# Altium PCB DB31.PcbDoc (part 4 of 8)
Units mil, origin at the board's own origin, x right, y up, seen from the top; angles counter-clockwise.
Board outline 3236.22 x 4456.69 mil, 8 copper layers (Top Layer, MidLayer1, MidLayer2, GND-Layer5, MidLayer3, VCC, MidLayer4, Bottom Layer), stack 61.8 mil thick; 226 components, 469 nets, 1815 pads, 1562 vias.
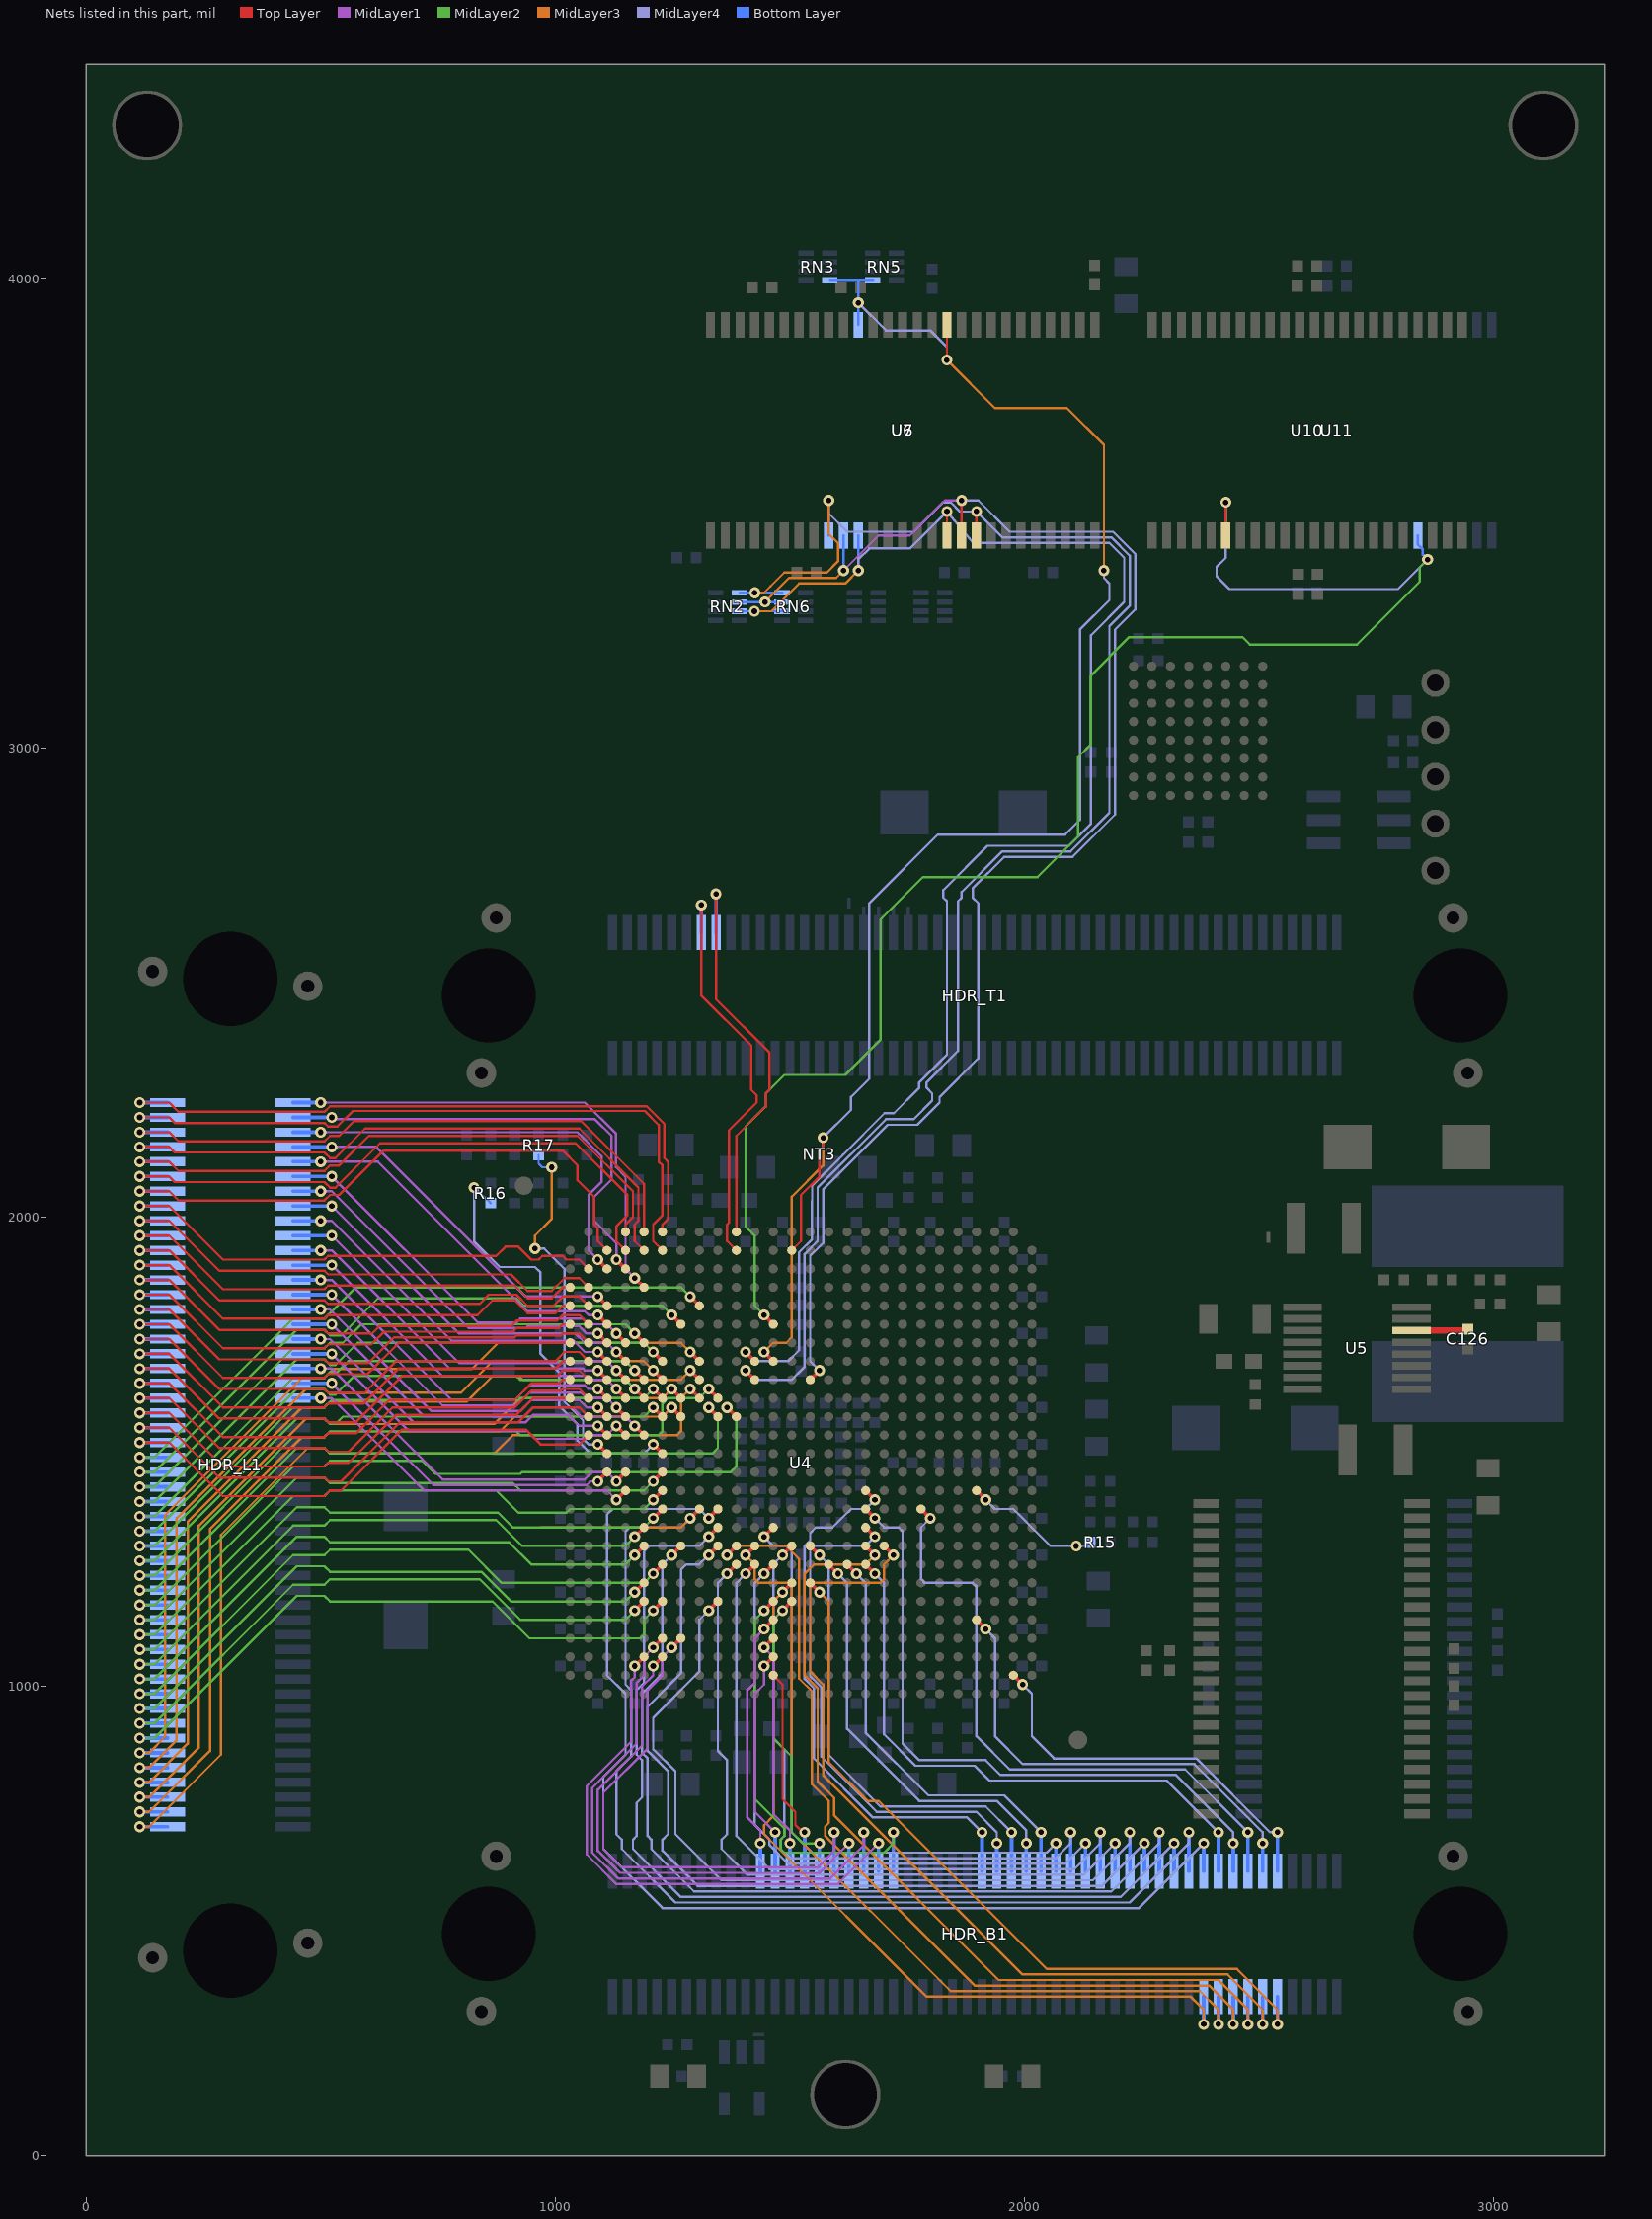
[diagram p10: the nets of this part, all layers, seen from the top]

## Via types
v1: diameter 23.62, hole 11.81, Top Layer to Bottom Layer, 947 vias
v2: diameter 23.62, hole 11.81, Top Layer to Bottom Layer, tented both sides, 476 vias
v3: diameter 27.56, hole 15.75, Top Layer to Bottom Layer, 138 vias
v4: diameter 23.62, hole 11.81, Top Layer to Bottom Layer, tented top, 1 vias

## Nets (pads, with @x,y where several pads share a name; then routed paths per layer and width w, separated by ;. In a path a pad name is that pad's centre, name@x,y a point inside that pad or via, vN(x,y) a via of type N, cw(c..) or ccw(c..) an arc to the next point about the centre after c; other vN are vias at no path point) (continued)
BUS_SDRAM_CLK: NT3.2 RN3.8 RN5.5 U4.H12 U6.38 U7.38 | length 3402.8
  Top Layer w5: NT3.2@1562.99,2141.73 1570.87,2149.61 v1(1570.87,2169.29) ; v2(1834.64,3826.77) U6.38@1834.65,3901.57
  Top Layer w7.87: v1(1444.88,1712.6) U4.H12@1464.57,1692.91
  MidLayer3 w5: v1(1444.88,1712.6) 1464.57,1732.28 1492.13,1732.28 1503.94,1744.09 1503.94,2031.49 1503.94,2039.37 1503.94,2043.31 1570.87,2110.24 v1(1570.87,2169.29) ; v2(1834.64,3826.77) 1937,3724.41 2090.55,3724.41 2169.29,3645.67 v1(2169.29,3377.95)
  MidLayer4 w5: v1(1570.87,2169.29) 1629.92,2228.35 1629.92,2255.91 1669.29,2295.28 1669.29,2669.29 1814.96,2814.96 2086.61,2814.96 2118.11,2846.46 2118.11,3251.97 2181.1,3314.96 2181.1,3350.39 2169.29,3362.2 v1(2169.29,3377.95) ; v2(1645.67,3948.82) 1704.72,3889.76 1799.21,3889.76 1834.64,3854.34 v2(1834.64,3826.77)
  Bottom Layer w5: RN3.8@1586.22,3996.06 RN5.5@1676.19,3996.06 RN5.5@1677.56,3996.06 ; U7.38@1645.67,3901.57 v2(1645.67,3948.82) 1645.67,3996.06
BUS_SDRAM_FEEDBACK: NT3.1 U4.B13 | length 221.3
  Top Layer w5: U4.B13@1503.94,1929.13 1523.62,1948.82 1523.62,2047.24 1562.99,2086.61 NT3.1@1562.99,2125.98
BUS_SDRAM_NCAS: RN2.7 RN6.6 U4.H11 U6.17 U7.17 | length 3407.4
  Top Layer w5: U6.17@1834.65,3452.76 1834.64,3499.99 v1(1834.65,3503.94)
  Top Layer w7.87: v1(1405.51,1712.6) U4.H11@1425.2,1692.91
  MidLayer3 w5: v1(1424.23,3291.34) 1460.63,3291.34 1519.68,3350.39 1618.11,3350.39 v2(1645.67,3377.95)
  MidLayer4 w5: v1(1405.51,1712.6) 1425.2,1692.91 1496.06,1692.91 1519.68,1716.54 1519.68,1925.2 1547.24,1952.76 1547.24,2031.5 1547.49,2039.37 1547.49,2067.18 1613.19,2132.87 1701.77,2221.46 1721.46,2221.46 1775.59,2275.59 1775.59,2287.4 1834.65,2346.46 1834.65,2673.23 1826.77,2681.1 1826.77,2696.85 1921.26,2791.34 2094.49,2791.34 2141.73,2838.58 2141.73,3240.16 2212.6,3311.02 2212.6,3405.51 2181.1,3437.01 1890.42,3437.01 v1(1834.65,3503.94) 1755.91,3425.2 1669.29,3425.2 1645.67,3401.57 v2(1645.67,3377.95)
  Bottom Layer w5: RN2.7@1393.3,3291.34 v1(1424.23,3291.34) RN6.6@1483.28,3291.34 RN6.6@1484.64,3291.34 ; v2(1645.67,3377.95) U7.17@1645.67,3452.76
BUS_SDRAM_NCS: RN2.5 RN6.8 U4.J11 U6.19 U7.19 | length 3648.5
  Top Layer w5: U6.19@1897.64,3452.76 v2(1897.63,3503.93)
  Top Layer w7.87: v1(1405.51,1673.23) U4.J11@1425.2,1653.54
  MidLayer3 w5: v1(1425.2,3330.71) 1444.88,3330.71 1458.54,3344.36 1488.19,3374.02 1578.74,3374.02 1602.36,3397.64 1602.36,3437.01 1582.68,3456.69 v2(1582.68,3527.56)
  MidLayer4 w5: v1(1405.51,1673.23) 1425.2,1653.54 1503.94,1653.54 1527.56,1677.16 ; 1519.68,1669.28 1531.5,1681.09 1531.5,1921.26 1559.06,1948.82 1559.06,2031.5 1559.06,2039.37 1559.06,2062.99 1704.72,2208.66 1763.78,2208.66 1803.15,2248.03 1803.15,2263.78 1791.34,2275.59 1791.34,2287.4 1858.27,2354.33 1858.27,2673.23 1866.14,2681.1 1866.14,2692.91 1952.76,2779.53 2098.43,2779.53 2181.1,2862.2 2181.1,3259.84 2224.41,3303.15 2224.41,3409.45 2185.04,3448.82 1952.76,3448.82 v2(1897.63,3503.93) 1862.21,3503.93 1842.52,3523.62 1826.77,3523.62 1763.78,3460.63 1622.05,3460.63 1582.68,3500 v2(1582.68,3527.56)
  Bottom Layer w5: RN2.5@1393.31,3330.71 v1(1425.2,3330.71) RN6.8@1483.28,3330.71 RN6.8@1484.26,3330.71 ; U7.19@1582.68,3452.76 v2(1582.68,3527.56)
BUS_SDRAM_NRAS: RN2.6 RN6.7 U4.J14 U6.18 U7.18 | length 3371.3
  Top Layer w5: U6.18@1866.14,3452.76 v1(1866.14,3527.55)
  Top Layer w7.87: U4.J14@1543.31,1653.54 v1(1562.99,1673.23)
  MidLayer1 w5: v2(1614.17,3377.95) 1688.98,3452.76 1755.91,3452.76 1830.7,3527.55 v1(1866.14,3527.55)
  MidLayer3 w5: v1(1446.86,3311.02) 1498.05,3362.2 1598.43,3362.2 v2(1614.17,3377.95)
  MidLayer4 w5: v1(1562.99,1673.23) 1543.31,1692.91 1543.31,1917.32 1570.87,1944.88 1570.87,2031.5 1570.87,2039.37 1570.87,2059.05 1708.66,2196.85 1771.65,2196.85 1818.9,2244.09 1818.9,2255.91 1901.57,2338.58 1901.57,2669.29 1889.76,2681.1 1889.76,2700.79 1956.69,2767.72 2102.36,2767.72 2192.91,2858.27 2192.91,3251.97 2236.22,3295.28 2236.22,3413.39 2188.98,3460.63 1968.5,3460.63 1901.58,3527.55 v1(1866.14,3527.55) v1@1858.27,3531.5
  Bottom Layer w5: RN2.6@1393.3,3311.02 v1(1446.86,3311.02) RN6.7@1483.28,3311.03 RN6.7@1484.64,3311.02 ; v2(1614.17,3377.95) U7.18@1614.17,3452.76
BUS_SRAM_NCS: U4.F12 U10.6 U11.6 | length 3565.7
  Top Layer w5: U10.6@2429.13,3452.76 2429.13,3503.94 v2(2429.13,3523.62)
  Top Layer w7.87: v1(1444.88,1791.34) U4.F12@1464.57,1771.65
  MidLayer2 w5: v1(1444.88,1791.34) 1425.2,1811.02 1425.2,1866.14 1425.2,1960.62 1405.51,1980.31 1405.51,2031.49 1405.51,2039.37 1405.51,2192.91 1448.82,2236.22 1448.82,2244.09 1448.82,2263.78 1488.19,2303.15 1618.11,2303.15 1692.91,2377.95 1692.91,2633.86 1783.46,2724.41 2027.56,2724.41 2114.17,2811.02 2114.17,2980.32 2141.73,3007.87 2141.73,3154.53 2223.42,3236.22 2464.57,3236.22 2480.32,3220.47 2708.66,3220.47 2842.52,3354.33 2842.52,3384.83 v2(2859.27,3401.57)
  MidLayer4 w5: v2(2429.13,3523.62) 2429.13,3405.51 2409.45,3385.83 2409.45,3366.14 2437.01,3338.58 2796.28,3338.58 v2(2859.27,3401.57)
  Bottom Layer w5: U11.6@2838.58,3452.76 2838.58,3433.42 2848.92,3423.08 2848.92,3411.92 v2(2859.27,3401.57)
BUZZER: HDR_B1.40 U4.AA12 | length 931.1
  Top Layer w7.87: v1(1444.88,1161.41) U4.AA12@1464.57,1181.1
  MidLayer2 w5: v1(1444.88,1161.41) 1425.2,1141.73 1425.2,921.26 1425.2,909.45 1425.2,759.84 1488.19,696.85 1488.19,681.1 1480.31,673.23 1480.31,653.54 1488.19,645.67 1700.79,645.67 1720.47,665.35 v2(1720.47,688.98)
  Bottom Layer w7.87: HDR_B1.40@1720.48,606.3 v2(1720.47,688.98)
CAN_RXD: HDR_T1.14 U4.B10 | length 878.4
  Top Layer w5: v2(1311.02,2665.35) 1311.02,2472.44 1417.32,2366.14 1417.32,2271.65 1429.13,2259.84 1429.13,2244.09 1370.08,2185.04 1370.08,2043.31 1370.08,2031.5 1370.08,1988.19 1366.14,1984.25 1366.14,1948.82 U4.B10@1385.83,1929.13
  Bottom Layer w7.87: HDR_T1.14@1311.02,2606.3 v2(1311.02,2665.35)
CAN_TXD: HDR_T1.16 U4.A10 | length 879.8
  Top Layer w5: v2(1342.52,2688.98) 1342.52,2464.57 1456.69,2350.39 1456.69,2271.66 1448.82,2263.78 1448.82,2236.22 1385.83,2173.23 1385.83,2043.31 1385.83,2031.5 U4.A10@1385.83,1968.5
  Bottom Layer w7.87: HDR_T1.16@1342.52,2606.3 v2(1342.52,2688.98)
COMP: C126.2 U5.6 | length 121.4
  Top Layer w13.78: U5.6@2824.58,1758.25 2942.3,1758.25 C126.2@2944.88,1760.82
CONF_DONE: R15.2 U4.R23 | length 302.6
  Top Layer w7.87: U4.R23@1897.64,1417.32 v1(1917.33,1397.64)
  MidLayer4 w5: v1(1917.33,1397.64) 1937.01,1377.95 1976.38,1377.95 2055.12,1299.21 v1(2110.24,1299.21)
  Bottom Layer w5: v1@2110.24,1307.08 v1(2110.24,1299.21) 2132.36,1299.21 R15.2@2140.23,1307.08
DATA0: R17.2 U4.N3 | length 760.6
  Top Layer w7.87: v1(1090.55,1515.75) U4.N3@1110.24,1496.06
  MidLayer3 w5: v1(956.69,1933.07) 956.69,1960.63 992.13,1996.06 v1(992.13,2106.3)
  MidLayer4 w5: v1(956.69,1933.07) 976.38,1933.07 1019.69,1889.76 1019.69,1606.3 1059.06,1566.93 1059.06,1527.56 1070.87,1515.75 v1(1090.55,1515.75)
  Bottom Layer w5: R17.2@964.56,2132.36 964.56,2114.18 972.44,2106.3 v1(992.13,2106.3)
DAU_RESET_SW: HDR_B1.38 U4.AD5 | length 1214.9
  Top Layer w7.87: v1(1169.29,1043.3) U4.AD5@1188.98,1062.99
  MidLayer1 w5: v1(1169.29,1043.3) 1169.29,1019.68 1161.42,1011.81 1161.42,921.26 1161.42,909.45 1161.42,881.89 1066.93,787.4 1066.93,641.73 1129.92,578.74 1602.36,578.74 v2(1688.98,665.35)
  Bottom Layer w7.87: HDR_B1.38@1688.98,606.3 v2(1688.98,665.35)
DAU_TFT_BLIGHT: HDR_B1.91 U4.Y14 | length 1664
  Top Layer w7.87: U4.Y14@1543.31,1220.47 v1(1562.99,1200.78)
  MidLayer3 w5: v1(1562.99,1200.78) 1582.68,1181.1 1582.68,921.26 1582.68,909.45 1582.68,838.58 1665.35,755.91 1688.98,755.91 2047.24,397.64 2452.76,397.64 2539.37,311.02 v2(2539.37,279.53)
  Bottom Layer w7.87: v2(2539.37,279.53) HDR_B1.91@2539.37,338.58
DAU_TFT_BLUE0: HDR_B1.62 U4.U12 | length 1346.5
  Top Layer w7.87: v1(1444.88,1318.9) U4.U12@1464.57,1338.58
  MidLayer4 w5: v1(1444.88,1318.9) 1464.57,1299.21 1492.13,1299.21 1503.94,1287.4 1503.94,921.26 1503.94,909.45 1503.94,688.98 1547.24,645.67 2047.24,645.67 v2(2066.93,665.35)
  Bottom Layer w7.87: HDR_B1.62@2066.93,606.3 v2(2066.93,665.35)
DAU_TFT_BLUE1: HDR_B1.64 U4.V13 | length 1420.6
  Top Layer w7.87: v1(1484.25,1279.53) U4.V13@1503.94,1299.21
  MidLayer4 w5: v1(1484.25,1279.53) 1464.57,1259.84 1464.57,921.26 1464.57,909.45 1464.57,889.76 1488.19,866.14 1488.19,681.1 1480.31,673.23 1480.31,653.54 1500,633.86 2066.93,633.86 2098.42,665.35 v2(2098.42,688.98)
  Bottom Layer w7.87: v2(2098.42,688.98) HDR_B1.64@2098.43,606.3
DAU_TFT_BLUE2: HDR_B1.66 U4.W12 | length 1394.3
  Top Layer w7.87: v1(1444.88,1240.16) U4.W12@1464.57,1259.84
  MidLayer4 w5: v1(1444.88,1240.16) 1425.2,1220.47 1425.2,921.26 1425.2,909.45 1425.2,704.72 1456.69,673.23 1456.69,661.42 1496.06,622.05 2086.62,622.05 v2(2129.92,665.35)
  Bottom Layer w7.87: HDR_B1.66@2129.92,606.3 v2(2129.92,665.35)
DAU_TFT_BLUE3: HDR_B1.68 U4.W11 | length 1529.1
  Top Layer w7.87: v1(1405.51,1240.16) U4.W11@1425.2,1259.84
  MidLayer4 w5: v1(1405.51,1240.16) 1385.83,1220.47 1385.83,921.26 1385.83,909.45 1385.83,681.1 1456.69,610.24 2106.3,610.24 2161.42,665.35 v2(2161.42,688.98)
  Bottom Layer w7.87: HDR_B1.68@2161.42,606.3 v2(2161.42,688.98)
DAU_TFT_BLUE4: HDR_B1.70 U4.W10 | length 1583.8
  Top Layer w7.87: v1(1366.14,1240.16) U4.W10@1385.83,1259.84
  MidLayer4 w5: v1(1366.14,1240.16) 1346.46,1220.47 1346.46,921.26 1346.46,909.45 1346.46,862.2 1366.14,842.52 1366.14,685.04 1354.33,673.23 1354.33,653.54 1409.45,598.43 2125.98,598.43 v2(2192.91,665.35)
  Bottom Layer w7.87: HDR_B1.70@2192.92,606.3 v2(2192.91,665.35)
DAU_TFT_CL1: HDR_B1.88 U4.T20 | length 1355.7
  Top Layer w7.87: U4.T20@1779.53,1377.95 v1(1799.22,1358.27)
  MidLayer4 w5: v1(1799.22,1358.27) 1779.53,1338.58 1779.53,1228.35 1787.4,1220.47 1889.76,1220.47 1897.64,1212.6 1897.64,921.26 1897.64,911.26 1897.64,893.7 1968.5,822.83 2342.52,822.83 v2@2476.38,688.98
  Bottom Layer w7.87: HDR_B1.88@2476.38,606.3 v2(2476.38,688.98)
DAU_TFT_CL2: HDR_B1.90 U4.AB23 | length 1061.7
  Top Layer w7.87: U4.AB23@1897.64,1141.73 v1(1917.33,1122.04)
  MidLayer4 w5: v1(1917.33,1122.04) 1937.01,1102.36 1937.01,921.26 1937.01,909.45 1937.01,893.7 1996.06,834.65 2362.2,834.65 2507.87,688.98 v2(2507.87,665.35)
  Bottom Layer w7.87: v2(2507.87,665.35) HDR_B1.90@2507.88,606.3 v2(2507.87,665.35)
DAU_TFT_CL3: HDR_B1.92 U4.AE25 | length 837.3
  Top Layer w7.87: U4.AE25@1976.38,1023.62 v1(1996.07,1003.94)
  MidLayer4 w5: v1(1996.07,1003.94) 2015.75,984.25 2015.75,921.26 2015.75,909.45 2015.75,893.7 2062.99,846.46 2366.14,846.46 2523.62,688.98 v2(2539.37,688.98)
  Bottom Layer w7.87: HDR_B1.92@2539.37,606.3 v2(2539.37,688.98)
DAU_TFT_DISP_ON: HDR_B1.89 U4.V18 | length 1898.8
  Top Layer w7.87: U4.V18@1700.79,1299.21 v1(1720.47,1279.53)
  MidLayer3 w5: v1(1720.47,1279.53) 1700.79,1259.84 1700.79,1228.35 1692.91,1220.47 1551.18,1220.47 1543.31,1212.6 1543.31,1031.49 1570.87,1003.94 1570.87,921.26 1570.87,909.45 1570.87,811.02 1996.06,385.83 2433.07,385.83 2507.87,311.02 v2(2507.88,279.53)
  Bottom Layer w7.87: v2(2507.88,279.53) HDR_B1.89@2507.88,338.58
DAU_TFT_GREEN0: HDR_B1.72 U4.AA9 | length 1720.9
  Top Layer w7.87: v1(1326.77,1161.42) U4.AA9@1346.46,1181.1
  MidLayer4 w5: v1(1326.77,1161.42) 1307.09,1141.73 1307.09,1031.5 1208.66,933.07 1208.66,921.26 1208.66,909.45 1208.66,866.14 1255.91,818.9 1255.91,685.04 1354.33,586.61 2145.67,586.61 2224.41,665.36 v2(2224.41,688.98)
  Bottom Layer w7.87: HDR_B1.72@2224.41,606.3 v2(2224.41,688.98)
DAU_TFT_GREEN1: HDR_B1.74 U4.V9 | length 1905.7
  Top Layer w7.87: v1(1326.77,1279.53) U4.V9@1346.46,1299.21
  MidLayer4 w5: v1(1326.77,1279.53) 1307.09,1259.84 1279.53,1259.84 1267.72,1248.03 1267.72,1027.56 1196.85,956.69 1196.85,921.26 1196.85,909.45 1196.85,862.2 1240.16,818.9 1240.16,685.04 1228.35,673.23 1228.35,649.61 1303.15,574.8 2165.35,574.8 v2(2255.9,665.35)
  Bottom Layer w7.87: HDR_B1.74@2255.91,606.3 v2(2255.9,665.35)
DAU_TFT_GREEN2: HDR_B1.76 U4.V7 | length 1957
  Top Layer w7.87: v1(1248.03,1279.53) U4.V7@1267.72,1299.21
  MidLayer4 w5: v1(1248.03,1279.53) 1228.35,1259.84 1228.35,1027.56 1185.04,984.25 1185.04,921.26 1185.04,909.45 1185.04,858.27 1196.85,846.46 1196.85,681.1 1204.72,673.23 1204.72,653.54 1295.28,562.99 2185.04,562.99 2287.4,665.35 v2(2287.4,688.98)
  Bottom Layer w7.87: HDR_B1.76@2287.41,606.3 v2(2287.4,688.98)
DAU_TFT_GREEN3: HDR_B1.78 U4.U9 | length 2134.4
  Top Layer w7.87: v1(1326.77,1318.9) U4.U9@1346.46,1338.58
  MidLayer4 w5: v1(1326.77,1318.9) 1307.09,1299.21 1200.79,1299.21 1188.98,1287.4 1188.98,1007.87 1173.23,992.13 1173.23,921.26 1173.23,909.45 1173.23,854.33 1185.04,842.52 1185.04,763.78 1173.23,751.97 1173.23,681.1 1165.35,673.23 1165.35,653.54 1267.72,551.18 2204.72,551.18 v2(2318.9,665.35)
  Bottom Layer w7.87: HDR_B1.78@2318.9,606.3 v2(2318.9,665.35)
DAU_TFT_GREEN4: HDR_B1.80 U4.T8 | length 2618.5
  Top Layer w7.87: v1(1287.4,1358.27) U4.T8@1307.09,1377.95
  MidLayer3 w5: 968.51,1338.58 1267.72,1338.58 v1(1287.4,1358.27)
  MidLayer4 w5: v1(1287.4,1358.27) 1267.72,1338.58 1157.48,1338.58 1149.61,1330.71 1149.61,1003.94 1161.42,992.13 1161.42,921.26 1161.42,909.45 1161.42,850.39 1129.92,818.9 1129.92,685.04 1141.73,673.23 1141.73,653.54 1255.91,539.37 2224.41,539.37 2350.39,665.35 v2(2350.39,688.98)
  Bottom Layer w7.87: HDR_B1.80@2350.4,606.3 v2(2350.39,688.98)
DAU_TFT_GREEN5: HDR_B1.82 U4.T9 | length 2453.7
  Top Layer w7.87: v1(1326.77,1358.27) U4.T9@1346.46,1377.95
  MidLayer4 w5: v1(1326.77,1358.27) 1307.09,1377.95 1122.05,1377.95 1110.24,1366.14 1110.24,1023.62 1149.61,984.25 1149.61,921.26 1149.61,909.45 1149.61,854.33 1102.36,807.09 1102.36,653.54 1228.35,527.56 2244.09,527.56 v2(2381.89,665.35)
  Bottom Layer w7.87: HDR_B1.82@2381.89,606.3 v2(2381.89,665.35)
DAU_TFT_IRQ: HDR_B1.81 U4.Y13 | length 1742.4
  Top Layer w7.87: v1(1484.25,1200.78) U4.Y13@1503.94,1220.47
  MidLayer3 w5: v1(1484.25,1200.78) 1464.57,1181.1 1464.57,921.26 1464.57,909.45 1464.57,723.43 1444.88,703.74 1444.88,685.04 1791.34,338.58 2354.33,338.58 2381.89,311.02 v2(2381.89,279.53)
  Bottom Layer w7.87: v2(2381.89,279.53) HDR_B1.81@2381.89,338.58
DAU_TFT_M: HDR_B1.87 U4.V17 | length 1879.3
  Top Layer w7.87: U4.V17@1661.42,1299.21 v1(1681.1,1279.53)
  MidLayer3 w5: v1(1681.1,1279.53) 1661.42,1259.84 1551.18,1259.84 1531.5,1240.16 1531.5,1160.43 1531.5,1023.62 1559.06,996.06 1559.06,921.26 1559.06,909.45 1559.06,797.24 1594.49,761.81 1594.49,724.41 1944.88,374.02 2413.39,374.02 2476.38,311.02 v2(2476.38,279.53)
  Bottom Layer w7.87: v2(2476.38,279.53) HDR_B1.87@2476.38,338.58
DAU_TFT_MUX: HDR_B1.85 U4.V10 | length 1934.8
  Top Layer w7.87: v1(1366.14,1279.53) U4.V10@1385.83,1299.21
  MidLayer3 w5: v1(1366.14,1279.53) 1385.83,1299.21 1492.13,1299.21 1519.68,1271.65 1519.68,1016.73 1547.24,989.17 1547.24,921.26 1547.24,909.45 1547.24,791.34 1582.68,755.91 1582.68,708.66 1574.8,700.79 1574.8,681.1 1893.7,362.2 2393.7,362.2 2444.88,311.02 v2(2444.88,279.53)
  Bottom Layer w7.87: v2(2444.88,279.53) HDR_B1.85@2444.89,338.58
DAU_TFT_POL: HDR_B1.83 U4.V11 | length 1852.6
  Top Layer w7.87: v1(1405.51,1279.53) U4.V11@1425.2,1299.21
  MidLayer3 w5: v1(1405.51,1279.53) 1425.2,1259.84 1425.2,1228.35 1433.07,1220.47 1496.06,1220.47 1503.94,1212.6 1503.94,921.26 1503.94,909.45 1503.94,688.98 1842.52,350.39 2374.02,350.39 2413.39,311.03 v2(2413.39,279.53)
  Bottom Layer w7.87: v2(2413.39,279.53) HDR_B1.83@2413.39,338.58
DAU_TFT_RED0: HDR_B1.52 U4.R17 | length 1194.5
  Top Layer w7.87: U4.R17@1661.42,1417.32 v1(1681.1,1397.64)
  MidLayer4 w5: v1(1681.1,1397.64) 1661.42,1377.95 1629.92,1377.95 1590.55,1338.58 1555.12,1338.58 1543.31,1326.77 1543.31,1311.02 1531.5,1299.21 1531.5,1015.75 1551.18,996.06 1551.18,921.26 1551.18,909.45 1551.18,846.46 1677.17,720.47 1870.08,720.47 1877.95,720.47 v2(1909.45,688.98)
  Bottom Layer w7.87: HDR_B1.52@1909.45,606.3 v2(1909.45,688.98)
DAU_TFT_RED1: HDR_B1.54 U4.U17 | length 1151.3
  Top Layer w7.87: U4.U17@1661.42,1338.58 v1(1681.1,1318.9)
  MidLayer4 w5: v1(1681.1,1318.9) 1661.42,1299.21 1551.18,1299.21 1543.31,1291.34 1543.31,1021.65 1566.93,998.03 1566.93,921.26 1566.93,909.45 1566.93,850.39 1685.04,732.28 1897.64,732.28 1940.94,688.98 v2(1940.94,665.35)
  Bottom Layer w7.87: HDR_B1.54@1940.95,606.3 v2(1940.94,665.35)
DAU_TFT_RED2: HDR_B1.56 U4.V14 | length 1002.1
  Top Layer w7.87: U4.V14@1543.31,1299.21 v1(1562.99,1279.53)
  MidLayer4 w5: v1(1562.99,1279.53) 1582.68,1259.84 1582.68,921.26 1582.68,909.45 1582.68,854.33 1692.91,744.1 1881.89,744.1 1917.32,744.09 v2(1972.44,688.98)
  Bottom Layer w7.87: HDR_B1.56@1972.44,606.3 v2(1972.44,688.98)
DAU_TFT_RED3: HDR_B1.58 U4.W15 | length 924.9
  Top Layer w7.87: U4.W15@1582.68,1259.84 v1(1602.36,1240.16)
  MidLayer4 w5: v1(1602.36,1240.16) 1622.05,1220.47 1622.05,921.26 1622.05,909.45 1775.59,755.91 1940.94,755.91 2003.94,692.92 v2(2003.94,665.35)
  Bottom Layer w7.87: HDR_B1.58@2003.94,606.3 v2(2003.94,665.35)
DAU_TFT_RED4: HDR_B1.60 U4.W16 | length 935.1
  Top Layer w7.87: U4.W16@1622.05,1259.84 v1(1641.73,1240.16)
  MidLayer4 w5: v1(1641.73,1240.16) 1661.42,1220.47 1661.42,921.26 1661.42,910.43 1661.42,901.57 1795.28,767.71 1956.69,767.71 ; 1940.94,767.72 1956.69,767.72 ; v2(2035.43,688.98) 1956.69,767.71
  Bottom Layer w7.87: HDR_B1.60@2035.44,606.3 v2(2035.43,688.98)
DAU_TFT_STH: HDR_B1.86 U4.T17 | length 1416.7
  Top Layer w7.87: U4.T17@1661.42,1377.95 v1(1681.1,1358.27)
  MidLayer4 w5: v1(1681.1,1358.27) 1700.79,1338.58 1732.28,1338.58 1740.16,1330.71 1740.16,921.26 1740.16,909.45 1740.16,877.95 1775.59,842.52 1917.32,842.52 1948.82,811.02 2322.84,811.02 2444.88,688.98 v2(2444.88,665.35)
  Bottom Layer w7.87: HDR_B1.86@2444.89,606.3 v2(2444.88,665.35)
DAU_TFT_STV: HDR_B1.84 U4.W17 | length 1260.2
  Top Layer w7.87: U4.W17@1661.42,1259.84 v1(1681.1,1240.16)
  MidLayer4 w5: v1(1681.1,1240.16) 1700.79,1220.47 1700.79,921.26 1700.79,911.26 1700.79,897.64 1767.72,830.71 1893.7,830.71 1925.2,799.21 2303.15,799.21 v2@2413.38,688.98
  Bottom Layer w7.87: HDR_B1.84@2413.39,606.3 v2(2413.38,688.98)
DCLK: R16.2 U4.N6 | length 931.9
  Top Layer w7.87: v1(1208.66,1515.75) U4.N6@1228.35,1496.06
  MidLayer4 w5: v1(826.77,2062.99) 826.77,1948.6 881.67,1893.7 956.69,1893.7 968.5,1881.89 968.5,1708.66 1007.87,1669.29 1007.87,1598.42 1047.24,1559.05 1047.24,1523.62 1059.88,1510.98 1074.8,1496.06 1188.98,1496.06 v1(1208.66,1515.75)
  Bottom Layer w5: v1(826.77,2062.99) 860.7,2031.5 R16.2@862.2,2030
DIP0: HDR_B1.22 U4.AB12 | length 569.7
  Top Layer w7.87: v1(1444.88,1122.04) U4.AB12@1464.57,1141.73
  MidLayer1 w5: v2(1437.01,665.35) 1437.01,692.91 1409.45,720.47 1409.45,909.45 1409.45,921.26 1409.45,992.13 1425.2,1007.87 1425.2,1102.36 v1(1444.88,1122.04)
  Bottom Layer w7.87: HDR_B1.22@1437.01,606.3 v2(1437.01,665.35)
DIP1: HDR_B1.24 U4.AD12 | length 490.9
  Top Layer w7.87: v1(1444.88,1043.3) U4.AD12@1464.57,1062.99
  MidLayer1 w5: v1(1444.88,1043.3) 1444.88,1003.93 1425.2,984.25 1425.2,921.26 1425.2,909.45 1425.2,732.28 v2(1468.5,688.98)
  Bottom Layer w7.87: HDR_B1.24@1468.51,606.3 v2(1468.5,688.98)
DIP2: HDR_B1.26 U4.AC12 | length 527
  Top Layer w7.87: v1(1444.88,1082.67) U4.AC12@1464.57,1102.36
  MidLayer1 w5: v1(1444.88,1082.67) 1464.57,1062.99 1464.57,921.26 1464.57,909.45 1464.57,728.35 1500,692.91 v2(1500,665.35)
  Bottom Layer w7.87: HDR_B1.26@1500,606.3 v2(1500,665.35)
DIP3: HDR_B1.28 U4.AE12 | length 447.4
  Top Layer w5: U4.AE12@1464.57,1023.62 1484.25,1003.93 1484.25,921.26 1484.25,909.45 1484.25,759.84 1511.81,732.28 1511.81,704.72 1527.56,688.98 v2(1531.5,688.98)
  Bottom Layer w7.87: HDR_B1.28@1531.5,606.3 v2(1531.5,688.98)
DIP4: HDR_B1.30 U4.AA13 | length 652.6
  Top Layer w7.87: v1(1484.25,1161.41) U4.AA13@1503.94,1181.1
  MidLayer2 w5: v1(1484.25,1161.41) 1464.57,1141.73 1464.57,921.26 1464.57,909.45 1464.57,889.76 1503.94,850.39 1503.94,688.98 1527.56,665.35 v2(1562.99,665.35)
  Bottom Layer w7.87: HDR_B1.30@1562.99,606.3 v2(1562.99,665.35)
DIP5: HDR_B1.32 U4.AC7 | length 1162.5
  Top Layer w7.87: v1(1248.03,1082.67) U4.AC7@1267.72,1102.36
  MidLayer1 w5: v1(1248.03,1082.67) 1228.35,1062.99 1228.35,1023.62 1196.85,992.12 1196.85,921.26 1196.85,909.45 1196.85,867.82 1102.36,773.33 1102.36,653.54 1141.73,614.17 1559.06,614.17 1594.49,649.61 v2(1594.49,688.98)
  Bottom Layer w7.87: HDR_B1.32@1594.49,606.3 v2(1594.49,688.98)
DIP6: HDR_B1.34 U4.AD6 | length 1110.6
  Top Layer w7.87: v1(1208.66,1043.3) U4.AD6@1228.35,1062.99
  MidLayer1 w5: v1(1208.66,1043.3) 1208.66,1023.62 1185.04,1000 1185.04,921.26 1185.04,909.45 1185.04,874.02 1090.55,779.53 1090.55,649.61 1137.8,602.36 1562.99,602.36 v2(1625.98,665.35)
  Bottom Layer w7.87: HDR_B1.34@1625.99,606.3 v2(1625.98,665.35)
DIP7: HDR_B1.36 U4.AC6 | length 1259.8
  Top Layer w7.87: v1(1208.66,1082.67) U4.AC6@1228.35,1102.36
  MidLayer1 w5: v1(1208.66,1082.67) 1188.98,1062.99 1188.98,1023.62 1173.23,1007.87 1173.23,921.26 1173.23,909.45 1173.23,877.95 1078.74,783.46 1078.74,645.67 1133.86,590.55 1586.61,590.55 1657.48,661.42 v2(1657.48,688.98)
  Bottom Layer w7.87: HDR_B1.36@1657.48,606.3 v2(1657.48,688.98)
EXTEND_A0: HDR_L1.1 U4.A6 | length 1467.7
  Top Layer w5: v2(114.17,2244.09) 177.17,2244.09 196.85,2224.41 409.45,2224.41 ; 385.83,2224.41 507.88,2224.41 519.69,2236.22 1194.66,2236.22 1232.28,2198.6 1232.28,2125.98 1240.16,2118.11 1240.16,2043.31 1240.16,2031.5 1240.16,1996.06 1228.35,1984.25 U4.A6@1228.35,1968.5
  Bottom Layer w7.87: v2(114.17,2244.09) HDR_L1.1@173.23,2244.09
EXTEND_A1: HDR_L1.3 U4.B6 | length 1533.7
  Top Layer w5: v2(114.17,2212.6) 153.54,2212.6 ; 137.8,2212.6 177.17,2212.6 188.98,2200.79 409.45,2200.79 ; 377.95,2200.79 507.88,2200.79 515.75,2192.91 535.43,2192.91 568.74,2226.22 1190.52,2226.22 1220.47,2196.27 1220.47,2118.11 1228.35,2110.24 1228.35,2043.31 1228.35,2031.5 1228.35,2003.94 1208.66,1984.25 1208.66,1948.82 U4.B6@1228.35,1929.13
  Bottom Layer w7.87: v2(114.17,2212.6) HDR_L1.3@173.23,2212.6
EXTEND_A2: HDR_L1.5 U4.A5 | length 1337.4
  Top Layer w5: v2(114.17,2181.1) 157.48,2181.1 ; 137.8,2181.1 177.17,2181.1 196.85,2161.42 507.88,2161.42 519.69,2173.23 539.37,2173.23 570.87,2204.72 1055.12,2204.72 1188.98,2070.87 1188.98,2043.31 1188.98,2031.5 U4.A5@1188.98,1968.5
  Bottom Layer w7.87: v2(114.17,2181.1) HDR_L1.5@173.23,2181.1
EXTEND_A3: HDR_L1.7 U4.B5 | length 1371.1
  Top Layer w5: v2(114.17,2149.61) 153.54,2149.61 ; 137.8,2149.61 177.17,2149.61 188.98,2137.8 507.88,2137.8 519.69,2125.98 531.5,2125.98 594.49,2188.98 1051.18,2188.98 1177.17,2062.99 1177.17,2043.31 1177.17,2031.5 1177.17,1992.12 1169.29,1984.25 1169.29,1948.82 U4.B5@1188.98,1929.13
  Bottom Layer w7.87: v2(114.17,2149.61) HDR_L1.7@173.23,2149.6
EXTEND_A4: HDR_L1.9 U4.A4 | length 1326.9
  Top Layer w5: v2(114.17,2118.11) 149.6,2118.11 ; 137.8,2118.11 177.17,2118.11 196.85,2098.43 409.45,2098.43 ; 385.83,2098.43 507.88,2098.43 519.69,2110.24 539.37,2110.24 602.36,2173.23 1047.24,2173.23 1165.35,2055.12 1165.35,2043.31 1165.35,2031.5 1165.35,2000 1149.61,1984.25 U4.A4@1149.61,1968.5
  Bottom Layer w7.87: v2(114.17,2118.11) HDR_L1.9@173.23,2118.11
EXTEND_A5: HDR_L1.11 U4.B4 | length 1340.9
  Top Layer w5: v2(114.17,2086.62) 149.61,2086.62 ; 137.8,2086.61 177.17,2086.61 188.98,2074.8 507.88,2074.8 519.69,2062.99 531.5,2062.99 625.98,2157.48 1043.31,2157.48 1153.54,2047.24 1153.54,2043.31 1153.54,2031.5 1153.54,2003.94 1129.92,1980.32 1129.92,1948.82 U4.B4@1149.61,1929.13
  Bottom Layer w7.87: v2(114.17,2086.62) HDR_L1.11@173.23,2086.61
EXTEND_A6: HDR_L1.13 U4.B3 | length 1300
  Top Layer w5: v2(114.17,2055.12) 149.61,2055.12 ; 137.8,2055.12 177.16,2055.12 196.85,2035.43 409.45,2035.43 ; 385.83,2035.43 507.88,2035.43 519.69,2047.24 539.37,2047.24 633.86,2141.73 1015.75,2141.73 1047.24,2110.24 1047.24,2078.74 1082.68,2043.31 1082.68,2031.5 1082.68,1984.25 1090.55,1976.38 1090.55,1948.82 U4.B3@1110.24,1929.13
  Bottom Layer w7.87: v2(114.17,2055.12) HDR_L1.13@173.23,2055.12
EXTEND_A7: HDR_L1.15 U4.C2 | length 1112.4
  Top Layer w5: v2(114.17,2023.62) 149.61,2023.62 ; 137.8,2023.62 177.16,2023.62 291.34,1909.45 507.87,1909.45 515.75,1917.32 874.02,1917.32 893.7,1937.01 921.26,1937.01 948.82,1909.45 964.57,1909.45 972.44,1917.32 1015.75,1917.32 1023.62,1909.45 1051.18,1909.45 U4.C2@1070.87,1889.76
  Bottom Layer w7.87: v2(114.17,2023.62) HDR_L1.15@173.23,2023.62
EXTEND_A8: HDR_L1.17 U4.D2 | length 1109.1
  Top Layer w5: v2(114.17,1992.13) 149.61,1992.13 ; 137.8,1992.13 177.16,1992.13 283.46,1885.83 507.87,1885.83 515.75,1877.95 905.51,1877.95 940.94,1842.52 956.69,1842.52 968.5,1842.52 992.13,1842.52 1019.68,1870.08 1051.18,1870.08 U4.D2@1070.87,1850.39
  Bottom Layer w7.87: v2(114.17,1992.13) HDR_L1.17@173.23,1992.12
EXTEND_A9: HDR_L1.19 U4.D1 | length 1059.9
  Top Layer w5: v2(114.17,1960.63) 149.61,1960.63 ; 137.8,1960.63 177.16,1960.63 291.34,1846.46 507.87,1846.46 515.75,1854.33 913.39,1854.33 940.94,1826.77 956.69,1826.77 968.5,1826.77 992.13,1826.77 1015.75,1850.39 U4.D1@1031.5,1850.39
  Bottom Layer w7.87: v2(114.17,1960.63) HDR_L1.19@173.23,1960.63
EXTEND_A10: HDR_L1.21 U4.E2 | length 1109.1
  Top Layer w5: v2(114.17,1929.13) 149.61,1929.13 ; 137.8,1929.13 177.16,1929.13 283.46,1822.83 507.87,1822.83 515.75,1814.96 838.58,1814.96 858.27,1834.65 917.32,1834.65 940.94,1811.02 956.69,1811.02 968.5,1811.02 996.06,1811.02 1015.75,1830.71 1051.18,1830.71 U4.E2@1070.87,1811.02
  Bottom Layer w7.87: v2(114.17,1929.13) HDR_L1.21@173.23,1929.13
EXTEND_A11: HDR_L1.23 U4.E1 | length 1069.7
  Top Layer w5: v2(114.17,1897.64) 149.61,1897.64 ; 137.8,1897.64 177.16,1897.64 291.34,1783.46 507.87,1783.46 515.75,1791.34 834.64,1791.34 866.14,1822.83 913.39,1822.83 940.94,1795.28 956.69,1795.28 968.5,1795.28 1000,1795.28 1015.75,1811.02 U4.E1@1031.5,1811.02
  Bottom Layer w7.87: v2(114.17,1897.64) HDR_L1.23@173.23,1897.64
EXTEND_A12: HDR_L1.25 U4.F2 | length 1099.3
  Top Layer w5: v2(114.17,1866.14) 149.61,1866.14 ; 137.8,1866.14 177.16,1866.14 283.46,1759.84 507.87,1759.84 515.75,1751.97 609.25,1751.97 625,1767.72 905.51,1767.72 917.32,1779.53 956.69,1779.53 968.5,1779.53 1003.94,1779.53 1015.75,1791.34 1051.18,1791.34 U4.F2@1070.87,1771.65
  Bottom Layer w7.87: v2(114.17,1866.14) HDR_L1.25@173.23,1866.14
EXTEND_A13: HDR_L1.27 U4.F1 | length 1056.7
  Top Layer w5: v2(114.17,1834.65) 149.61,1834.65 ; 137.8,1834.65 177.16,1834.65 291.34,1720.47 507.87,1720.47 515.75,1728.35 607.28,1728.35 634.84,1755.91 909.45,1755.91 917.32,1763.78 956.69,1763.78 968.5,1763.78 1007.87,1763.78 1015.75,1771.65 U4.F1@1031.5,1771.65
  Bottom Layer w7.87: v2(114.17,1834.65) HDR_L1.27@173.23,1834.64
EXTEND_A14: HDR_L1.29 U4.G2 | length 1105.2
  Top Layer w5: v2(114.17,1803.15) 145.67,1803.15 ; 137.8,1803.15 177.16,1803.15 283.46,1696.85 507.87,1696.85 515.75,1688.98 601.38,1688.98 656.5,1744.09 913.39,1744.09 917.32,1748.03 956.69,1748.03 968.5,1748.03 1011.81,1748.03 1015.75,1751.97 1051.18,1751.97 U4.G2@1070.87,1732.28
  Bottom Layer w7.87: v2(114.17,1803.15) HDR_L1.29@173.23,1803.15
EXTEND_A15: HDR_L1.31 U4.G1 | length 1062.5
  Top Layer w5: v2(114.17,1771.65) 145.67,1771.65 ; 137.8,1771.65 177.16,1771.65 291.34,1657.48 507.87,1657.48 515.75,1665.35 599.41,1665.35 666.34,1732.28 956.69,1732.28 968.5,1732.28 U4.G1@1031.5,1732.28
  Bottom Layer w7.87: v2(114.17,1771.65) HDR_L1.31@173.23,1771.65
EXTEND_A16: HDR_L1.33 U4.H2 | length 1114.9
  Top Layer w5: v2(114.17,1740.16) 145.67,1740.16 ; 137.8,1740.16 177.16,1740.16 283.46,1633.86 507.87,1633.86 515.75,1625.98 593.5,1625.98 660.43,1692.91 956.69,1692.91 968.5,1692.91 1000,1692.91 1019.68,1712.6 1051.18,1712.6 U4.H2@1070.87,1692.91
  Bottom Layer w7.87: v2(114.17,1740.16) HDR_L1.33@173.23,1740.15
EXTEND_A17: HDR_L1.35 U4.H1 | length 1076.3
  Top Layer w5: v2(114.17,1708.66) 149.61,1708.66 ; 137.8,1708.66 177.16,1708.66 291.34,1594.49 507.87,1594.49 515.75,1602.36 590.55,1602.36 665.36,1677.17 956.69,1677.17 968.5,1677.17 1000,1677.17 1015.75,1692.91 U4.H1@1031.5,1692.91
  Bottom Layer w7.87: v2(114.17,1708.66) HDR_L1.35@173.23,1708.66
EXTEND_A18: HDR_L1.37 U4.J2 | length 1128.7
  Top Layer w5: v2(114.17,1677.17) 149.61,1677.17 ; 137.8,1677.17 177.16,1677.17 283.46,1570.86 507.87,1570.86 515.75,1562.99 574.8,1562.99 673.23,1661.42 956.69,1661.42 968.5,1661.42 1003.94,1661.42 1015.75,1673.23 1051.18,1673.23 U4.J2@1070.87,1653.54
  Bottom Layer w7.87: v2(114.17,1677.17) HDR_L1.37@173.23,1677.16
EXTEND_A19: HDR_L1.39 U4.J1 | length 1086
  Top Layer w5: v2(114.17,1645.67) 149.61,1645.67 ; 137.8,1645.67 177.16,1645.67 291.34,1531.49 507.87,1531.49 515.75,1539.37 574.8,1539.37 645.67,1610.24 913.39,1610.24 948.82,1645.67 956.69,1645.67 968.5,1645.67 1007.88,1645.67 1015.75,1653.54 U4.J1@1031.5,1653.54
  Bottom Layer w7.87: v2(114.17,1645.67) HDR_L1.39@173.23,1645.67
EXTEND_A20: HDR_L1.41 U4.K2 | length 1138.4
  Top Layer w5: v2(114.17,1614.17) 149.61,1614.17 ; 137.8,1614.17 177.16,1614.17 283.46,1507.87 507.87,1507.87 515.75,1500 559.05,1500 653.54,1594.49 913.39,1594.49 948.82,1629.92 956.69,1629.92 968.5,1629.92 1011.81,1629.92 1015.75,1633.86 1051.18,1633.86 U4.K2@1070.87,1614.17
  Bottom Layer w7.87: v2(114.17,1614.17) HDR_L1.41@173.23,1614.17
EXTEND_A21: HDR_L1.43 U4.K1 | length 1095.8
  Top Layer w5: v2(114.17,1582.68) 149.61,1582.68 ; 137.8,1582.68 177.16,1582.68 291.34,1468.5 507.87,1468.5 515.75,1476.38 559.05,1476.38 661.42,1578.74 917.32,1578.74 952.76,1614.17 956.69,1614.17 968.5,1614.17 U4.K1@1031.5,1614.17
  Bottom Layer w7.87: v2(114.17,1582.68) HDR_L1.43@173.23,1582.67
EXTEND_A22: HDR_L1.45 U4.L2 | length 1136.4
  Top Layer w5: v2(114.17,1551.18) 177.16,1551.18 283.46,1444.88 507.87,1444.88 515.75,1437.01 543.31,1437.01 669.29,1562.99 921.26,1562.99 952.76,1594.49 956.69,1594.49 968.5,1594.49 1051.18,1594.49 U4.L2@1070.87,1574.8
  Bottom Layer w7.87: v2(114.17,1551.18) HDR_L1.45@173.23,1551.18
EXTEND_A23: HDR_L1.47 U4.M2 | length 1154.8
  Top Layer w5: v2(114.17,1519.69) 149.61,1519.69 ; 137.8,1519.69 177.16,1519.69 291.34,1405.51 507.87,1405.51 519.68,1417.32 543.31,1417.32 673.23,1547.24 937.01,1547.24 968.5,1515.75 1051.18,1515.75 U4.M2@1070.87,1535.43
  Bottom Layer w7.87: v2(114.17,1519.69) HDR_L1.47@173.23,1519.68
EXTEND_A24: HDR_L1.49 U4.E8 | length 1418.3
  Top Layer w7.87: v1(1287.4,1830.71) U4.E8@1307.09,1811.02
  MidLayer2 w5: v2(114.17,1488.19) 145.67,1488.19 440.94,1783.46 507.87,1783.46 574.8,1850.39 956.69,1850.39 968.5,1850.39 1267.72,1850.39 v1(1287.4,1830.71)
  Bottom Layer w7.87: v2(114.17,1488.19) HDR_L1.49@173.23,1488.19
EXTEND_A25: HDR_L1.51 U4.F7 | length 1398.5
  Top Layer w7.87: v1(1248.03,1791.34) U4.F7@1267.72,1771.65
  MidLayer2 w5: v2(114.17,1456.69) 145.67,1456.69 448.82,1759.84 507.87,1759.84 519.68,1748.03 543.31,1748.03 622.05,1826.77 917.32,1826.77 933.07,1811.02 956.69,1811.02 968.51,1811.03 1228.35,1811.03 v1(1248.03,1791.34)
  Bottom Layer w7.87: v2(114.17,1456.69) HDR_L1.51@173.23,1456.69
EXTEND_A26: HDR_L1.53 U4.G5 | length 1293.7
  Top Layer w7.87: v1(1169.29,1751.97) U4.G5@1188.98,1732.28
  MidLayer2 w5: v2(114.17,1425.2) 145.67,1425.2 440.94,1720.47 507.87,1720.47 519.69,1732.28 547.24,1732.28 586.61,1771.65 956.69,1771.65 968.51,1771.65 1149.61,1771.65 v1(1169.29,1751.97)
  Bottom Layer w7.87: v2(114.17,1425.2) HDR_L1.53@173.23,1425.19
EXTEND_A27: HDR_L1.55 U4.H6 | length 1339.6
  Top Layer w7.87: v1(1208.66,1712.6) U4.H6@1228.35,1692.91
  MidLayer2 w5: v2(114.17,1393.7) 145.67,1393.7 448.81,1696.85 507.87,1696.85 519.68,1685.04 531.5,1685.04 578.74,1732.28 956.69,1732.28 968.51,1732.28 1188.98,1732.29 v1(1208.66,1712.6)
  Bottom Layer w7.87: v2(114.17,1393.7) HDR_L1.55@173.23,1393.7
EXTEND_A28: HDR_L1.57 U4.J5 | length 1287.2
  Top Layer w7.87: v1(1169.29,1673.23) U4.J5@1188.98,1653.54
  MidLayer2 w5: v2(114.17,1362.21) 145.67,1362.21 440.94,1657.48 507.87,1657.48 519.69,1669.29 535.43,1669.29 559.06,1692.91 956.69,1692.91 968.51,1692.91 1149.61,1692.91 v1(1169.29,1673.23)
  Bottom Layer w7.87: v2(114.17,1362.21) HDR_L1.57@173.23,1362.2
EXTEND_A29: HDR_L1.59 U4.K5 | length 1300.2
  Top Layer w7.87: v1(1169.29,1633.86) U4.K5@1188.98,1614.17
  MidLayer2 w5: v2(114.17,1330.71) 145.67,1330.71 448.81,1633.86 507.87,1633.86 519.68,1622.05 531.5,1622.05 570.87,1661.42 917.32,1661.42 925.2,1653.54 956.69,1653.54 968.51,1653.54 1149.61,1653.54 v1(1169.29,1633.86)
  Bottom Layer w7.87: v2(114.17,1330.71) HDR_L1.59@173.23,1330.71
EXTEND_A30: HDR_L1.61 U4.K6 | length 1320
  Top Layer w7.87: v1(1208.66,1633.86) U4.K6@1228.35,1614.17
  MidLayer2 w5: v2(114.17,1299.21) 145.67,1299.21 440.94,1594.49 507.87,1594.49 523.62,1610.24 921.26,1610.24 925.2,1614.17 956.69,1614.17 968.51,1614.18 1188.98,1614.17 v1(1208.66,1633.86)
  Bottom Layer w7.87: v2(114.17,1299.21) HDR_L1.61@173.23,1299.21
EXTEND_A31: HDR_L1.63 U4.L6 | length 1326.5
  Top Layer w7.87: v1(1208.66,1594.49) U4.L6@1228.35,1574.8
  MidLayer2 w5: v2(114.17,1267.72) 145.67,1267.72 448.81,1570.86 507.87,1570.86 519.68,1559.05 531.49,1559.05 547.24,1574.8 956.69,1574.8 968.51,1574.81 1188.98,1574.8 v1(1208.66,1594.49)
  Bottom Layer w7.87: v2(114.17,1267.72) HDR_L1.63@173.23,1267.71
EXTEND_A32: HDR_L1.65 U4.K9 | length 1505.3
  Top Layer w7.87: v1(1326.77,1633.86) U4.K9@1346.46,1614.17
  MidLayer2 w5: v2(114.17,1236.22) 145.67,1236.22 440.94,1531.49 507.87,1531.49 519.69,1543.31 917.32,1543.31 925.2,1535.43 956.69,1535.43 968.51,1535.43 1220.47,1535.43 1228.35,1543.31 1228.35,1602.36 1240.16,1614.17 1307.09,1614.17 v1(1326.77,1633.86)
  Bottom Layer w7.87: v2(114.17,1236.22) HDR_L1.65@173.23,1236.22
EXTEND_A33: HDR_L1.67 U4.L9 | length 1549.3
  Top Layer w7.87: v1(1326.77,1594.49) U4.L9@1346.46,1574.8
  MidLayer2 w5: v2(114.17,1204.72) 145.67,1204.72 448.81,1507.87 507.87,1507.87 519.68,1496.06 956.69,1496.06 968.51,1496.06 1334.65,1496.06 1346.46,1507.87 1346.46,1574.8 v1(1326.77,1594.49)
  Bottom Layer w7.87: v2(114.17,1204.72) HDR_L1.67@173.23,1204.72
EXTEND_A34: HDR_L1.69 U4.L10 | length 1637.8
  Top Layer w7.87: v1(1366.14,1594.49) U4.L10@1385.83,1574.8
  MidLayer2 w5: v2(114.17,1173.23) 145.67,1173.23 440.94,1468.5 507.87,1468.5 519.69,1480.31 716.54,1480.31 744.09,1452.76 925.2,1452.76 929.13,1456.69 956.69,1456.69 968.51,1456.69 1374.02,1456.69 1385.83,1468.5 1385.83,1574.8 v1(1366.14,1594.49)
  Bottom Layer w7.87: v2(114.17,1173.23) HDR_L1.69@173.23,1173.23
EXTEND_A35: HDR_L1.71 U4.P6 | length 1326.5
  Top Layer w7.87: v1(1208.66,1437.01) U4.P6@1228.35,1456.69
  MidLayer2 w5: v2(114.17,1141.73) 145.67,1141.73 448.81,1444.88 507.87,1444.88 519.68,1433.07 909.45,1433.07 925.2,1417.32 956.69,1417.32 968.51,1417.33 1188.98,1417.32 v1(1208.66,1437.01)
  Bottom Layer w7.87: v2(114.17,1141.73) HDR_L1.71@173.23,1141.73
EXTEND_A36: HDR_L1.73 U4.R6 | length 1339.6
  Top Layer w7.87: v1(1208.66,1397.64) U4.R6@1228.35,1417.32
  MidLayer2 w5: v2(114.17,1110.24) 145.67,1110.24 440.94,1405.51 507.87,1405.51 519.69,1417.32 874.02,1417.32 921.26,1370.08 956.69,1370.08 968.51,1370.08 1023.63,1370.08 1031.5,1377.96 1133.86,1377.95 1188.98,1377.95 v1(1208.66,1397.64)
  Bottom Layer w7.87: v2(114.17,1110.24) HDR_L1.73@173.23,1110.23
EXTEND_A37: HDR_L1.75 U4.T6 | length 1333
  Top Layer w7.87: v1(1208.66,1358.27) U4.T6@1228.35,1377.95
  MidLayer2 w5: v2(114.17,1078.74) 145.67,1078.74 448.81,1381.89 507.87,1381.89 519.68,1370.08 877.95,1370.08 909.45,1338.58 956.69,1338.58 968.51,1338.59 1188.98,1338.58 v1(1208.66,1358.27)
  Bottom Layer w7.87: v2(114.17,1078.74) HDR_L1.75@173.23,1078.74
EXTEND_A38: HDR_L1.77 U4.U5 | length 1300.2
  Top Layer w7.87: v1(1169.29,1318.9) U4.U5@1188.98,1338.58
  MidLayer2 w5: v2(114.17,1047.24) 145.67,1047.24 440.94,1342.52 507.87,1342.52 519.69,1354.33 874.02,1354.33 929.13,1299.21 956.69,1299.21 968.51,1299.21 1149.61,1299.21 v1(1169.29,1318.9)
  Bottom Layer w7.87: v2(114.17,1047.24) HDR_L1.77@173.23,1047.24
EXTEND_A39: HDR_L1.79 U4.V5 | length 1300.2
  Top Layer w7.87: v1(1169.29,1279.53) U4.V5@1188.98,1299.21
  MidLayer2 w5: v2(114.17,1015.75) 145.67,1015.75 448.81,1318.9 507.87,1318.9 519.68,1307.09 901.58,1307.09 948.82,1259.84 956.69,1259.84 968.51,1259.84 1149.61,1259.84 v1(1169.29,1279.53)
  Bottom Layer w7.87: v2(114.17,1015.75) HDR_L1.79@173.23,1015.74
EXTEND_A40: HDR_L1.81 U4.W6 | length 1346.1
  Top Layer w7.87: v1(1208.66,1240.16) U4.W6@1228.35,1259.84
  MidLayer2 w5: v2(114.17,984.25) 145.67,984.25 440.94,1279.53 507.87,1279.53 519.69,1291.34 814.96,1291.34 885.83,1220.47 956.69,1220.47 968.51,1220.47 1188.98,1220.47 v1(1208.66,1240.16)
  Bottom Layer w7.87: v2(114.17,984.25) HDR_L1.81@173.23,984.25
EXTEND_A41: HDR_L1.83 U4.Y5 | length 1306.7
  Top Layer w7.87: v1(1169.29,1200.78) U4.Y5@1188.98,1220.47
  MidLayer2 w5: v2(114.17,952.76) 145.67,952.75 448.81,1255.9 507.87,1255.9 519.69,1244.09 842.52,1244.09 905.51,1181.1 956.69,1181.1 968.51,1181.1 1149.61,1181.1 v1(1169.29,1200.78)
  Bottom Layer w7.87: v2(114.17,952.76) HDR_L1.83@173.23,952.75
EXTEND_A42: HDR_L1.85 U4.AA5 | length 1313.2
  Top Layer w7.87: v1(1169.29,1161.41) U4.AA5@1188.98,1181.1
  MidLayer2 w5: v2(114.17,921.26) 145.67,921.26 440.94,1216.53 507.87,1216.53 519.69,1228.34 838.58,1228.34 925.2,1141.73 956.69,1141.73 968.51,1141.73 1149.61,1141.73 v1(1169.29,1161.41)
  Bottom Layer w7.87: v2(114.17,921.26) HDR_L1.85@173.23,921.26
EXTEND_A43: HDR_L1.87 U4.AA6 | length 1387.4
  Top Layer w7.87: v1(1208.66,1161.41) U4.AA6@1228.35,1181.1
  MidLayer2 w5: v2(114.17,889.76) 145.67,889.76 448.81,1192.91 507.87,1192.91 519.69,1181.1 866.14,1181.1 944.88,1102.36 956.69,1102.36 968.5,1102.36 1181.1,1102.36 1188.98,1110.24 1188.98,1141.73 v1(1208.66,1161.41)
  Bottom Layer w7.87: v2(114.17,889.76) HDR_L1.87@173.23,889.76
EXTEND_A44: HDR_L1.89 U4.H8 | length 1907.1
  Top Layer w7.87: v1(1287.4,1712.6) U4.H8@1307.09,1692.91
  MidLayer3 w5: v2(114.17,858.27) 133.86,858.27 168.4,892.81 168.4,1365.25 460.63,1657.48 507.87,1657.48 526.57,1676.18 821.85,1676.18 877.95,1732.28 956.69,1732.28 968.5,1732.28 1267.72,1732.28 v1(1287.4,1712.6)
  Bottom Layer w7.87: v2(114.17,858.27) HDR_L1.89@173.23,858.26
EXTEND_A45: HDR_L1.91 U4.J6 | length 1831.6
  Top Layer w7.87: v1(1208.66,1673.23) U4.J6@1228.35,1653.54
  MidLayer3 w5: v2(114.17,826.77) 133.86,826.77 192.91,885.83 192.91,1358.27 468.5,1633.86 507.87,1633.86 515.75,1625.98 799.21,1625.98 866.14,1692.91 956.69,1692.91 968.51,1692.91 1188.98,1692.91 v1(1208.66,1673.23)
  Bottom Layer w7.87: v2(114.17,826.77) HDR_L1.91@173.23,826.77
EXTEND_A46: HDR_L1.93 U4.J8 | length 1907.1
  Top Layer w7.87: v1(1287.4,1673.23) U4.J8@1307.09,1653.54
  MidLayer3 w5: v2(114.17,795.28) 133.86,795.28 216.54,877.95 216.54,1350.39 460.63,1594.49 507.87,1594.49 519.68,1606.3 811.02,1606.3 866.14,1661.42 922.24,1661.42 930.12,1653.54 956.69,1653.54 968.51,1653.54 1267.72,1653.54 v1(1287.4,1673.23)
  Bottom Layer w7.87: v2(114.17,795.28) HDR_L1.93@173.23,795.27
EXTEND_A47: HDR_L1.95 U4.K7 | length 1867.7
  Top Layer w7.87: v1(1248.03,1633.86) U4.K7@1267.72,1614.17
  MidLayer3 w5: v2(114.17,763.78) 133.86,763.78 240.16,870.08 240.16,1342.52 468.5,1570.87 507.87,1570.87 519.68,1559.06 870.08,1559.06 925.2,1614.17 956.69,1614.17 968.51,1614.17 1228.35,1614.17 v1(1248.03,1633.86)
  Bottom Layer w7.87: v2(114.17,763.78) HDR_L1.95@173.23,763.78
EXTEND_A48: HDR_L1.97 U4.L7 | length 1854.9
  Top Layer w7.87: v1(1248.03,1594.49) U4.L7@1267.72,1574.8
  MidLayer3 w5: v2(114.17,732.28) 133.86,732.28 263.78,862.2 263.78,1334.65 460.63,1531.5 508.35,1531.5 508.35,1531.97 519.68,1543.31 881.89,1543.31 913.39,1574.8 956.69,1574.8 968.51,1574.8 1228.35,1574.8 v1(1248.03,1594.49)
  Bottom Layer w7.87: v2(114.17,732.28) HDR_L1.97@173.23,732.28
EXTEND_A49: HDR_L1.99 U4.K8 | length 1972.4
  Top Layer w7.87: v1(1287.4,1633.86) U4.K8@1307.09,1614.17
  MidLayer3 w5: v2(114.17,700.79) 133.86,700.79 287.4,854.33 287.4,1322.83 472.44,1507.87 507.87,1507.87 519.68,1496.06 870.08,1496.06 909.45,1535.43 956.69,1535.43 968.51,1535.43 1259.84,1535.43 1267.72,1543.31 1267.72,1614.17 v1(1287.4,1633.86)
  Bottom Layer w7.87: v2(114.17,700.79) HDR_L1.99@173.23,700.78
EXTEND_B0: HDR_L1.2 U4.D5 | length 1070.7
  Top Layer w7.87: v1(1169.29,1870.08) U4.D5@1188.98,1850.39
  MidLayer1 w5: v2(500,2244.1) 1062.99,2244.1 1129.53,2177.56 1129.53,2106.69 1149.61,2086.61 1149.61,2039.37 1149.61,2031.5 1149.61,1889.76 v1(1169.29,1870.08) ; v1@1167.32,1868.11 v1@1169.28,1866.15
  Bottom Layer w7.87: HDR_L1.2@440.94,2244.09 v2(500,2244.1)
EXTEND_B1: HDR_L1.4 U4.C4 | length 1021.5
  Top Layer w7.87: v1(1129.92,1909.45) U4.C4@1149.61,1889.76
  MidLayer1 w5: v2(523.62,2212.6) 527.56,2212.6 531.5,2208.66 1084.28,2208.66 1119.53,2173.42 1119.53,2080.16 1082.68,2043.31 1082.68,2039.37 1082.68,2031.5 1082.68,1992.13 1129.92,1944.88 v1(1129.92,1909.45)
  Bottom Layer w7.87: HDR_L1.4@440.94,2212.6 v2(523.62,2212.6)
EXTEND_B2: HDR_L1.6 U4.C3 | length 946.6
  Top Layer w7.87: v1(1090.55,1909.45) U4.C3@1110.24,1889.76
  MidLayer1 w5: v2(500,2181.1) 1047.24,2181.1 1098.43,2129.92 1098.43,2074.8 1070.87,2047.24 1070.87,1929.13 v1(1090.55,1909.45)
  Bottom Layer w7.87: HDR_L1.6@440.94,2181.1 v2(500,2181.1)
EXTEND_B3: HDR_L1.8 U4.E3 | length 809.5
  Top Layer w7.87: v1(1090.55,1830.71) U4.E3@1110.24,1811.02
  MidLayer1 w5: v2(523.62,2149.61) 618.11,2149.61 937.01,1830.71 956.69,1830.71 968.5,1830.71 v1(1090.55,1830.71)
  Bottom Layer w7.87: HDR_L1.8@440.94,2149.6 v2(523.62,2149.61)
EXTEND_B4: HDR_L1.10 U4.F3 | length 812.8
  Top Layer w7.87: v1(1090.55,1791.34) U4.F3@1110.24,1771.65
  MidLayer1 w5: v2(500,2118.11) 622.05,2118.11 940.94,1799.21 956.69,1799.21 968.5,1799.21 1063,1799.21 1070.87,1791.34 v1@1090.55,1791.34
  Bottom Layer w7.87: HDR_L1.10@440.94,2118.11 v2(500,2118.11)
EXTEND_B5: HDR_L1.12 U4.G4 | length 862
  Top Layer w7.87: v1(1129.92,1751.97) U4.G4@1149.61,1732.28
  MidLayer1 w5: v2(523.62,2086.62) 834.65,1775.59 917.32,1775.59 925.2,1783.46 956.69,1783.46 968.5,1783.46 1059.05,1783.46 1070.87,1771.65 1110.24,1771.65 v1(1129.92,1751.97)
  Bottom Layer w7.87: HDR_L1.12@440.94,2086.61 v2(523.62,2086.62)
EXTEND_B6: HDR_L1.14 U4.G3 | length 806.3
  Top Layer w7.87: v1(1090.55,1751.97) U4.G3@1110.24,1732.28
  MidLayer1 w5: v2(500,2055.12) 523.62,2055.12 814.96,1763.78 937.01,1763.78 940.94,1767.72 956.69,1767.72 968.5,1767.72 1051.18,1767.72 1066.93,1751.97 v1@1090.55,1751.97
  Bottom Layer w7.87: HDR_L1.14@440.94,2055.12 v2(500,2055.12)
EXTEND_B7: HDR_L1.16 U4.H4 | length 845.6
  Top Layer w7.87: v1(1129.92,1712.6) U4.H4@1149.61,1692.91
  MidLayer1 w5: v2(523.62,2023.62) 795.28,1751.97 956.69,1751.97 968.5,1751.97 1043.31,1751.97 1062.99,1732.28 1110.24,1732.28 v1(1129.92,1712.6)
  Bottom Layer w7.87: HDR_L1.16@440.94,2023.62 v2(523.62,2023.62)
EXTEND_B8: HDR_L1.18 U4.H3 | length 793.2
  Top Layer w7.87: v1(1090.55,1712.6) U4.H3@1110.24,1692.91
  MidLayer1 w5: v2(500,1992.13) 523.62,1992.13 779.53,1736.22 956.69,1736.22 968.5,1736.22 1039.37,1736.22 1062.99,1712.6 v1@1090.55,1712.6
  Bottom Layer w7.87: HDR_L1.18@440.94,1992.12 v2(500,1992.13)
EXTEND_B9: HDR_L1.20 U4.J4 | length 839.1
  Top Layer w7.87: v1(1129.92,1673.23) U4.J4@1149.61,1653.54
  MidLayer1 w5: v2(523.62,1960.63) 795.28,1688.98 956.69,1688.98 968.5,1688.98 1059.05,1688.98 1062.99,1692.91 1110.24,1692.91 v1(1129.92,1673.23)
  Bottom Layer w7.87: HDR_L1.20@440.94,1960.63 v2(523.62,1960.63)
EXTEND_B10: HDR_L1.22 U4.J3 | length 783.4
  Top Layer w7.87: v1(1090.55,1673.23) U4.J3@1110.24,1653.54
  MidLayer1 w5: v2(500,1929.14) 523.62,1929.14 775.59,1677.17 956.69,1677.17 968.51,1677.17 1059.06,1677.17 1062.99,1673.23 v1@1090.55,1673.23
  Bottom Layer w7.87: HDR_L1.22@440.94,1929.13 v2(500,1929.14)
EXTEND_B11: HDR_L1.24 U4.K4 | length 826.1
  Top Layer w7.87: v1(1129.92,1633.86) U4.K4@1149.61,1614.17
  MidLayer1 w5: v2(523.62,1897.64) 759.84,1661.42 956.69,1661.42 968.5,1661.42 1066.93,1661.42 1074.8,1653.54 1110.24,1653.54 v1(1129.92,1633.86)
  Bottom Layer w7.87: HDR_L1.24@440.94,1897.64 v2(523.62,1897.64)
EXTEND_B12: HDR_L1.26 U4.K3 | length 799.8
  Top Layer w7.87: v1(1090.55,1633.86) U4.K3@1110.24,1614.17
  MidLayer1 w5: v2(500,1866.14) 523.62,1866.14 779.53,1610.24 913.38,1610.24 944.88,1641.73 956.69,1641.73 968.5,1641.73 1062.99,1641.73 1070.87,1633.86 v1(1090.55,1633.86)
  Bottom Layer w7.87: HDR_L1.26@440.94,1866.14 v2(500,1866.14)
EXTEND_B13: HDR_L1.28 U4.L4 | length 839.1
  Top Layer w7.87: v1(1129.92,1594.49) U4.L4@1149.61,1574.8
  MidLayer1 w5: v2(523.62,1834.65) 759.84,1598.43 917.32,1598.43 944.88,1625.99 956.69,1625.99 968.5,1625.98 1055.12,1625.98 1066.93,1614.17 1110.24,1614.17 v1(1129.92,1594.49)
  Bottom Layer w7.87: HDR_L1.28@440.94,1834.64 v2(523.62,1834.65)
EXTEND_B14: HDR_L1.30 U4.L3 | length 783.4
  Top Layer w7.87: v1(1090.55,1594.49) U4.L3@1110.24,1574.8
  MidLayer1 w5: v2(500,1803.15) 519.68,1803.15 736.22,1586.61 925.2,1586.61 948.82,1610.24 956.69,1610.24 968.5,1610.24 1051.18,1610.24 1066.93,1594.49 v1(1090.55,1594.49)
  Bottom Layer w7.87: HDR_L1.30@440.94,1803.15 v2(500,1803.15)
EXTEND_B15: HDR_L1.32 U4.M5 | length 862.2
  Top Layer w7.87: v1(1169.29,1555.12) U4.M5@1188.98,1535.43
  MidLayer1 w5: v2(523.62,1771.66) 720.48,1574.8 933.07,1574.8 952.76,1594.49 956.69,1594.49 968.5,1594.49 1035.43,1594.49 1055.12,1574.8 1149.61,1574.8 v1(1169.29,1555.12)
  Bottom Layer w7.87: HDR_L1.32@440.94,1771.65 v2(523.62,1771.66)
EXTEND_B16: HDR_L1.34 U4.M3 | length 767.1
  Top Layer w7.87: v1(1090.55,1555.12) U4.M3@1110.24,1535.43
  MidLayer1 w5: v2(500,1740.16) 519.68,1740.16 696.85,1562.99 937.01,1562.99 952.76,1578.74 956.69,1578.74 968.5,1578.74 1027.56,1578.74 1051.18,1555.12 v1@1090.55,1555.12
  Bottom Layer w7.87: HDR_L1.34@440.94,1740.15 v2(500,1740.16)
EXTEND_B17: HDR_L1.36 U4.M4 | length 803.2
  Top Layer w7.87: v1(1129.92,1555.12) U4.M4@1149.61,1535.43
  MidLayer1 w5: v2(523.62,1708.66) 688.98,1543.31 940.94,1543.31 956.69,1527.56 968.5,1527.56 1070.87,1527.56 1078.74,1535.43 1110.23,1535.43 v1(1129.92,1555.12)
  Bottom Layer w7.87: HDR_L1.36@440.94,1708.66 v2(523.62,1708.66)
EXTEND_B18: HDR_L1.38 U4.P4 | length 829.3
  Top Layer w7.87: v1(1129.92,1437.01) U4.P4@1149.61,1456.69
  MidLayer1 w5: v2(500,1677.17) 523.62,1677.17 759.84,1440.94 956.69,1440.94 968.5,1440.94 1062.99,1440.94 1078.74,1456.69 1110.23,1456.69 v1(1129.92,1437.01)
  Bottom Layer w7.87: HDR_L1.38@440.94,1677.16 v2(500,1677.17)
EXTEND_B19: HDR_L1.40 U4.P3 | length 770.4
  Top Layer w7.87: v1(1090.55,1437.01) U4.P3@1110.24,1456.69
  MidLayer1 w5: v2(523.62,1645.67) 740.16,1429.13 956.69,1429.13 968.5,1429.13 1066.93,1429.13 1074.8,1437.01 v1(1090.55,1437.01)
  Bottom Layer w7.87: HDR_L1.40@440.94,1645.67 v2(523.62,1645.67)
EXTEND_B20: HDR_L1.42 U4.R4 | length 806.5
  Top Layer w7.87: v1(1129.92,1397.64) U4.R4@1149.61,1417.32
  MidLayer1 w5: v2(500,1614.17) 523.62,1614.17 641.73,1496.06 720.47,1417.32 956.69,1417.32 968.5,1417.32 1110.23,1417.32 v1(1129.92,1397.64)
  Bottom Layer w7.87: HDR_L1.42@440.94,1614.17 v2(500,1614.17)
